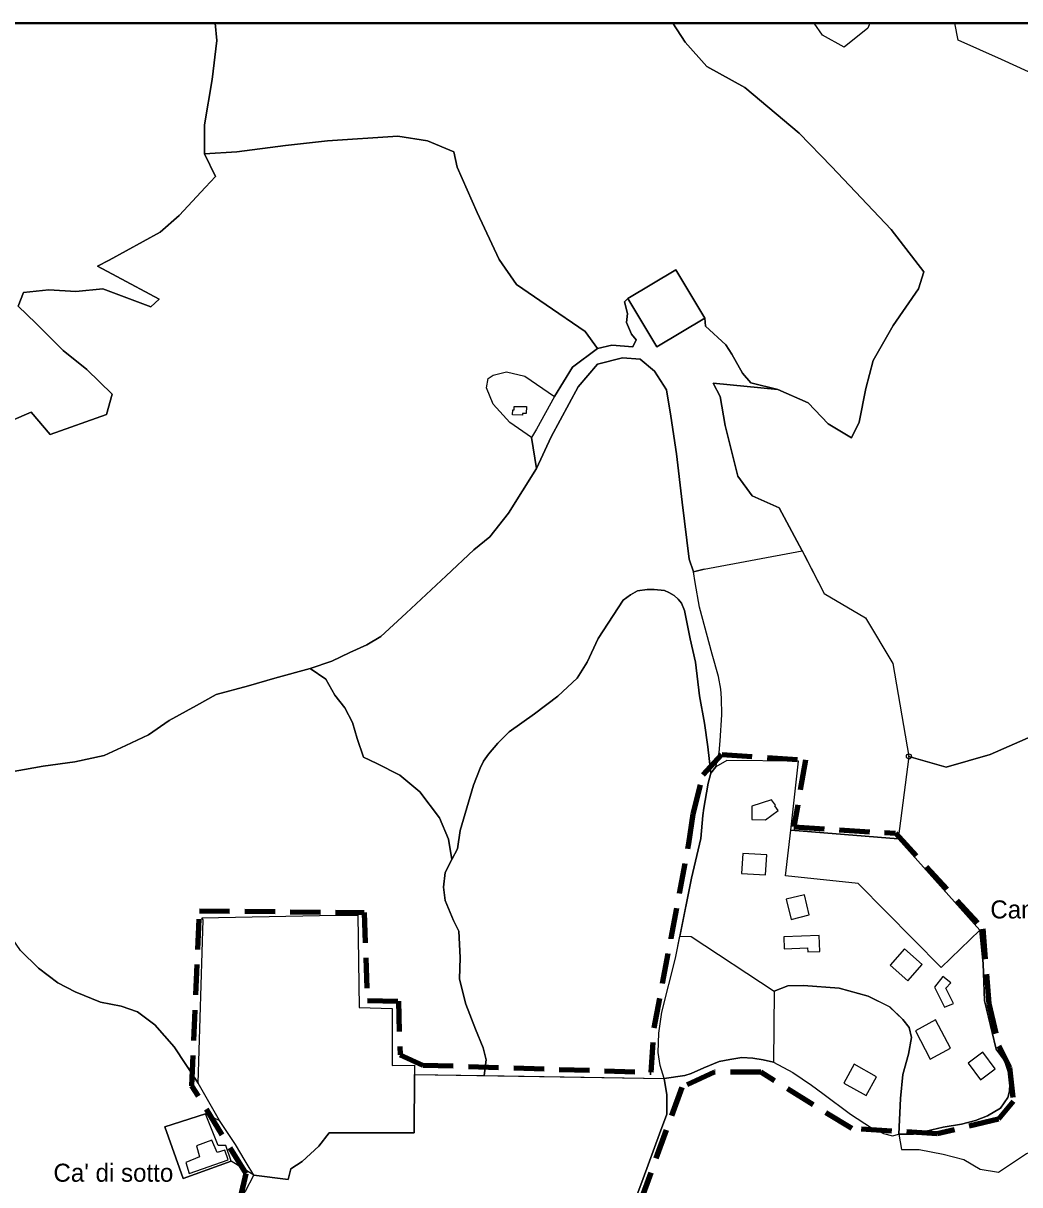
# Model space of a CAD drawing. Extents: x 650468 to 655025, y 889970 to 891591.
# Drawn here: x 654074 to 654626, y 890947 to 891591 of the extents above; entities that cross this region are included whole.
import ezdxf
from ezdxf.enums import TextEntityAlignment as Align

# ---------------------------------------------------------------- set-up
doc = ezdxf.new("R2010")
doc.units = 0
doc.header["$LTSCALE"] = 5.6
doc.header["$PDMODE"] = 32
doc.header["$PDSIZE"] = 2.8
doc.linetypes.add('MEDIUM_DASHED', pattern=[4.5, 3, -1.5])
for name, color, linetype, lineweight in [('11', 7, 'Continuous', 25), ('13', 7, 'Continuous', 25), ('19', 7, 'Continuous', 25), ('2', 7, 'Continuous', 25), ('20', 7, 'Continuous', 25), ('25', 7, 'Continuous', 25), ('31', 7, 'Continuous', 25), ('34', 7, 'Continuous', 25), ('35', 7, 'Continuous', 25), ('36', 7, 'Continuous', 25), ('37', 7, 'Continuous', 25), ('38', 7, 'Continuous', 25), ('6', 7, 'Continuous', 25), ('61', 7, 'Continuous', 35), ('7', 7, 'MEDIUM_DASHED', 100), ('9', 7, 'Continuous', 25)]:
    doc.layers.add(name, color=color, linetype=linetype, lineweight=lineweight)
doc.layers.add('60', color=7, linetype='Continuous')

msp = doc.modelspace()

# ---------------------------------------------------------------- linework, layer by layer
at = {"layer": '11'}
for points in [[(654526.26, 891055.98), (654506.53, 891057.59), (654497.91, 891057.32), (654490.26, 891054.44), (654489.91, 891015), (654500.51, 891009.32), (654510.97, 891002.25), (654517.19, 890997.65), (654532.5, 890986.24), (654544.32, 890978.54), (654550.97, 890975.53)], [(654550.97, 890975.53), (654555.85, 890974.15), (654559.47, 890975.16), (654560.32, 890994.86), (654561.56, 891008.17), (654564.69, 891019.43), (654566.47, 891028.65), (654565.2, 891034.24), (654561.54, 891038.72), (654554.31, 891045.73), (654542.37, 891051.66), (654526.26, 891055.98)]]:
    msp.add_lwpolyline(points, dxfattribs=at)
msp.add_lwpolyline([(654534.59, 891013.81), (654528.84, 891003.43), (654541.28, 890996.54), (654547.03, 891006.93)], close=True, dxfattribs=at)
at = {"layer": '13'}
msp.add_lwpolyline([(654536.84, 891114.1), (654496.59, 891118.38), (654499.46, 891143.65), (654558.94, 891138.76), (654604.36, 891088.18), (654582.8, 891067.48)], close=True, dxfattribs=at)
at = {"layer": '19'}
for points in [[(654429.2, 891006), (654427.06, 891013.1), (654425.98, 891020.44), (654426.23, 891030.98), (654427.86, 891042.64), (654435.45, 891072.74), (654437.93, 891084.93), (654444.24, 891084.76), (654490.26, 891054.43), (654489.92, 891015), (654484.13, 891016.32)], [(654459.83, 891015.42), (654451.3, 891011.91), (654444.28, 891008.65), (654440.77, 891007.64)], [(654472.29, 891017.59), (654465.59, 891016.55), (654459.83, 891015.42)], [(654484.13, 891016.32), (654478.38, 891017.18), (654472.29, 891017.59)], [(654197, 890943.46), (654201.61, 890952.4), (654220.7, 890949.89), (654222.24, 890955.88), (654228.41, 890959.87), (654237.67, 890968.35), (654243.33, 890975.84), (654290.52, 890975.84), (654290.66, 891008.15), (654429.2, 891006.01), (654430.69, 890996.86), (654430.8, 890986.12), (654426.65, 890975.27), (654417.62, 890950.54), (654399.53, 890902.06)], [(654429.2, 891006), (654440.77, 891007.64), (654429.2, 891006)]]:
    msp.add_lwpolyline(points, dxfattribs=at)
at = {"layer": '2'}
for points in [[(654355.64, 891361.3), (654343.64, 891369.61), (654334.42, 891379.77), (654330.73, 891389), (654331.65, 891394.08), (654334.42, 891395.93), (654341.8, 891397.77), (654351.95, 891395.47), (654368.48, 891384.09), (654358.44, 891365.96)], [(654346.09, 891378.51), (654352.88, 891378.5), (654352.75, 891374.65), (654350.73, 891374.6), (654350.73, 891373.83), (654345.19, 891373.88), (654345.24, 891376.67), (654346.1, 891376.7)], [(654174.81, 890986.42), (654152.28, 890979.05), (654162.37, 890950.57), (654189.01, 890960.03), (654186.08, 890968.75), (654181.78, 890968.75)], [(654163.9, 890959.42), (654165.81, 890953.25), (654187.43, 890960.84), (654185.5, 890966.13), (654181.37, 890964.98), (654178.39, 890971.71), (654169.84, 890968.53), (654171.57, 890962.48)]]:
    msp.add_lwpolyline(points, close=True, dxfattribs=at)
at = {"layer": '20'}
msp.add_lwpolyline([(654170.7, 891003.42), (654173.53, 891093.84), (654172.84, 891095.11), (654238.1, 891096.23), (654259.27, 891096.59), (654260.04, 891045.35), (654278.3, 891044.68), (654278.3, 891013.18), (654290.68, 891013.25), (654290.66, 891008.14), (654290.52, 890975.83), (654243.33, 890975.83), (654237.67, 890968.34), (654228.41, 890959.86), (654222.24, 890955.87), (654220.7, 890949.88), (654201.61, 890952.39), (654197.33, 890959.4), (654196.75, 890960.37), (654191.41, 890969.29), (654182.54, 890982.69)], close=True, dxfattribs=at)
at = {"layer": '25'}
msp.add_line((654304.53, 891150.42), (654309.67, 891138.66), dxfattribs=at)
for points in [[(654443.13, 891293.92), (654439.19, 891325.48), (654436.03, 891352.3), (654432.88, 891373.21), (654430.51, 891387.81), (654423.81, 891398.07), (654415.93, 891404.77), (654406.07, 891405.56), (654392.27, 891402.01), (654381.62, 891389.39)], [(654381.62, 891389.39), (654366.64, 891361.77), (654358.34, 891344.23), (654342.85, 891319.37), (654332.51, 891306.2), (654323.58, 891299), (654308.24, 891284.73), (654286.16, 891263.89), (654272.06, 891251.04)], [(654460.58, 891221.89), (654459.45, 891228.79), (654455.94, 891241.21), (654448.92, 891267.3), (654446.44, 891281.01), (654445.53, 891286.81), (654443.13, 891293.92)], [(654381.03, 891227.93), (654386.61, 891236.8), (654392.58, 891249.96), (654406.53, 891271.24), (654410.57, 891274.04), (654414.53, 891276.28), (654419.86, 891277.14), (654423.72, 891277.17), (654429.35, 891276.54), (654431.87, 891275.45), (654434.75, 891273.82), (654437.01, 891271.69), (654438.89, 891269.43), (654440.52, 891265.42), (654443.65, 891249.74), (654446.54, 891236.83), (654448.91, 891218.14), (654451.55, 891202.95), (654453.43, 891189.78), (654455.19, 891175.23), (654457.94, 891178.74)], [(654272.06, 891251.04), (654264.39, 891246.34), (654254.95, 891242.22)], [(654254.95, 891242.22), (654244.81, 891237.41), (654232.91, 891233.34)], [(654232.91, 891233.34), (654241.51, 891227.39), (654246.48, 891218.52), (654252.15, 891211.42), (654256.41, 891203.26), (654258.89, 891194.38), (654262.5, 891184.14), (654269.86, 891180.69), (654282.54, 891174.11), (654293.66, 891164.86), (654304.53, 891150.42)], [(654357.32, 891208.06), (654370.26, 891217.89), (654381.03, 891227.93)], [(654461.13, 891207.55), (654460.95, 891216.75), (654460.58, 891221.89)], [(654316.12, 891143.4), (654323.53, 891168.61), (654327.09, 891177.94), (654328.95, 891181.9), (654331.83, 891185.81), (654337.04, 891191.9), (654343.34, 891198.07), (654357.32, 891208.06)], [(654457.94, 891178.74), (654459.83, 891186.77), (654460.33, 891193.17), (654461.13, 891207.55)], [(654309.67, 891138.66), (654311.38, 891127.3), (654314.57, 891133.33), (654316.12, 891143.4)]]:
    msp.add_lwpolyline(points, dxfattribs=at)
at = {"layer": '31'}
for points in [[(654453.43, 891189.78), (654451.55, 891202.95), (654448.91, 891218.14), (654446.54, 891236.83), (654443.65, 891249.74), (654440.52, 891265.42), (654438.89, 891269.43), (654437.01, 891271.69), (654434.75, 891273.82), (654431.87, 891275.45), (654429.35, 891276.54), (654423.72, 891277.17), (654419.86, 891277.14), (654414.53, 891276.28), (654410.57, 891274.04), (654406.53, 891271.24), (654392.58, 891249.96), (654386.61, 891236.8), (654381.03, 891227.93)], [(654381.03, 891227.93), (654370.26, 891217.89), (654357.32, 891208.06)], [(654357.32, 891208.06), (654343.34, 891198.07), (654337.04, 891191.9), (654331.83, 891185.81), (654328.95, 891181.9), (654327.09, 891177.94), (654323.53, 891168.61), (654316.12, 891143.4)], [(654453.67, 891169.74), (654455.19, 891175.23), (654453.43, 891189.78)], [(654315.28, 891087.55), (654315.99, 891073), (654315.64, 891060.93), (654319.18, 891047.09), (654324.5, 891033.25), (654328.76, 891022.96), (654330.53, 891016.22), (654329.47, 891007.54), (654429.2, 891006), (654427.06, 891013.1), (654425.98, 891020.44), (654426.23, 891030.98), (654427.86, 891042.64), (654435.45, 891072.74), (654444.46, 891116.93), (654449.6, 891139.03), (654450.77, 891151.68), (654451.25, 891155.87), (654452.7, 891164.42), (654453.67, 891169.74)], [(654316.12, 891143.4), (654314.57, 891133.33), (654311.38, 891127.3), (654307.83, 891120.2), (654306.77, 891112.04), (654307.83, 891104.59), (654312.44, 891093.58), (654315.28, 891087.55)]]:
    msp.add_lwpolyline(points, dxfattribs=at)
at = {"layer": '34'}
for p, q in [((654451.42, 891288.44), (654445.53, 891286.81)), ((654463.91, 891182.3), (654457.94, 891178.74))]:
    msp.add_line(p, q, dxfattribs=at)
for points in [[(654451.42, 891288.44), (654505.84, 891298.44), (654517.93, 891274.94), (654540.98, 891261.33), (654556.01, 891236.06), (654565.03, 891184.54), (654558.94, 891138.75), (654499.46, 891143.64), (654503.73, 891181.86), (654463.91, 891182.3)], [(654460.58, 891221.89), (654459.45, 891228.79), (654455.94, 891241.21), (654448.92, 891267.3), (654446.44, 891281.01), (654445.53, 891286.81), (654451.42, 891288.44)], [(654461.13, 891207.55), (654460.95, 891216.75), (654460.58, 891221.89)], [(654457.94, 891178.74), (654459.83, 891186.77), (654460.33, 891193.17), (654461.13, 891207.55)]]:
    msp.add_lwpolyline(points, dxfattribs=at)
at = {"layer": '35'}
for points in [[(654723.35, 891275.91), (654713.14, 891269.98), (654703.64, 891271.74), (654691.89, 891279.49), (654681.27, 891273), (654666.24, 891247.72), (654655.21, 891218.56), (654655.63, 891201.68), (654634.17, 891196.2), (654610.12, 891185.51), (654585.63, 891178.66), (654565.03, 891184.54), (654558.94, 891138.75), (654604.36, 891088.17)], [(654232.91, 891233.34), (654213.2, 891227.88), (654198.73, 891223.66), (654180.66, 891218.84), (654169.81, 891212.81), (654154.75, 891204.37), (654143.3, 891196.53), (654130.65, 891190.5), (654118.59, 891185.08), (654102.33, 891181.46), (654084.85, 891179.05), (654060.75, 891174.83)], [(654262.5, 891184.14), (654258.89, 891194.38), (654256.41, 891203.26), (654252.15, 891211.42), (654246.48, 891218.52), (654241.51, 891227.39), (654232.91, 891233.34)], [(654315.28, 891087.55), (654312.44, 891093.58), (654307.83, 891104.59), (654306.77, 891112.04), (654307.83, 891120.2), (654311.38, 891127.3), (654309.67, 891138.66), (654304.53, 891150.42), (654293.66, 891164.86), (654282.54, 891174.11), (654269.86, 891180.69), (654262.5, 891184.14)], [(654170.7, 891003.42), (654173.53, 891093.84), (654172.84, 891095.11), (654238.1, 891096.23), (654259.27, 891096.59), (654260.04, 891045.35), (654278.3, 891044.68), (654278.3, 891013.18), (654290.68, 891013.25), (654290.66, 891008.14), (654329.47, 891007.54), (654330.53, 891016.22)], [(654324.5, 891033.25), (654319.18, 891047.09), (654315.64, 891060.93), (654315.99, 891073), (654315.28, 891087.55)], [(654604.36, 891088.17), (654606.19, 891069.58), (654606.98, 891049.07), (654613.39, 891022.17), (654618.04, 891015.89), (654620.59, 891008.2)], [(654072.27, 891076.98), (654082.2, 891067.04), (654092.89, 891059.02)], [(654092.89, 891059.02), (654102.44, 891054.05), (654116.57, 891048.32), (654128.02, 891046.03), (654137.18, 891042.97), (654146.73, 891035.72), (654157.42, 891023.49), (654170.7, 891003.42)], [(654330.53, 891016.22), (654328.76, 891022.96), (654324.5, 891033.25)], [(654440.77, 891007.64), (654444.28, 891008.65), (654451.3, 891011.91), (654459.83, 891015.42)], [(654459.83, 891015.42), (654465.59, 891016.55), (654472.29, 891017.59)], [(654472.29, 891017.59), (654478.38, 891017.18), (654484.13, 891016.32), (654489.92, 891015), (654489.91, 891014.99), (654500.51, 891009.31), (654510.97, 891002.24), (654517.19, 890997.64), (654532.5, 890986.23), (654544.32, 890978.53), (654550.97, 890975.52)], [(654620.59, 891008.2), (654620.91, 891002.74), (654620.79, 890998.86), (654619.82, 890995.48), (654615.7, 890989.49), (654608.63, 890985.18), (654601.98, 890982.67), (654594.08, 890980.67), (654583.93, 890979.04), (654574.53, 890976.78), (654567.51, 890975.15), (654559.47, 890975.15), (654560.8, 890966.6)], [(654398.63, 890870.86), (654393.91, 890872.3), (654388.18, 890871.68), (654391.04, 890877.21), (654399.53, 890902.05), (654417.62, 890950.53), (654426.65, 890975.26), (654430.8, 890986.11), (654430.69, 890996.85), (654429.2, 891006), (654440.77, 891007.64)], [(654614.69, 890954.07), (654630.14, 890964.31), (654692.09, 890985.03), (654685.79, 890974.85), (654668.7, 890958.56), (654656.4, 890945.47), (654631.8, 890929.74), (654613.87, 890916.44), (654587.96, 890904.47), (654561.39, 890894.84), (654542.79, 890888.85), (654523.19, 890882.21)], [(654550.97, 890975.52), (654555.85, 890974.14), (654559.47, 890975.15), (654560.8, 890966.6)], [(654560.8, 890966.6), (654570.67, 890966.6), (654583.91, 890964.06), (654595.44, 890960.94), (654604.46, 890955.58), (654614.69, 890954.07)], [(654560.8, 890966.6), (654570.67, 890966.6), (654583.91, 890964.06), (654595.44, 890960.94), (654604.46, 890955.58), (654614.69, 890954.07), (654630.14, 890964.31)]]:
    msp.add_lwpolyline(points, dxfattribs=at)
at = {"layer": '36'}
for points in [[(654056.47, 891366.24), (654078.16, 891375.45), (654088.61, 891362.95), (654119.83, 891374.16), (654123.07, 891385.36), (654108.99, 891399.14), (654095.84, 891409.66), (654080.73, 891424.8), (654070.84, 891434.15), (654073.82, 891441.86), (654087.95, 891443.22), (654102.92, 891442.36), (654117.85, 891443.86), (654144.46, 891433.9), (654149.18, 891438.13), (654125.56, 891450.58), (654114.9, 891456.38), (654121.47, 891459.67), (654149.68, 891475.18), (654160.2, 891484.4), (654174.8, 891500.1), (654180.29, 891506.06), (654174.34, 891518.7), (654174.34, 891534.8), (654178.49, 891559.96), (654181.08, 891581.59), (654180.27, 891591.08), (653618.27, 891591.08)], [(654631.32, 891564.12), (654616.29, 891570.92), (654592.24, 891581.61), (654590.46, 891591.08), (654543.37, 891591.08), (654542.13, 891588.42), (654529.11, 891577.73), (654517.08, 891584.53), (654512.48, 891591.08), (654434.08, 891591.08), (654440.93, 891580.64), (654452.95, 891567.03), (654473.99, 891555.37), (654504.06, 891530.09), (654522.09, 891511.62), (654555.16, 891476.63), (654573.2, 891453.3), (654570.22, 891443.86), (654556.2, 891423.44), (654545.17, 891404), (654541.16, 891388.45), (654537.37, 891369.8), (654533.15, 891361.23), (654520.12, 891369.01), (654509.1, 891380.67), (654492.37, 891388.06), (654456.37, 891391.56), (654460.37, 891384.06)], [(654460.37, 891384.06), (654463, 891368.03), (654470.02, 891339.84), (654478.12, 891329.02), (654493.07, 891322.34), (654507.09, 891296.1), (654517.93, 891274.94), (654540.98, 891261.33), (654556.01, 891236.06), (654565.03, 891184.54)], [(654565.03, 891184.54), (654585.63, 891178.66), (654610.12, 891185.51), (654634.17, 891196.2)]]:
    msp.add_lwpolyline(points, dxfattribs=at)
msp.add_point((654565.03, 891184.54), dxfattribs=at)
at = {"layer": '37'}
for points in [[(654477.25, 891391.72), (654492.37, 891388.06), (654509.1, 891380.67), (654520.12, 891369.01), (654533.15, 891361.23), (654537.37, 891369.8), (654541.16, 891388.45), (654545.17, 891404), (654556.2, 891423.44), (654570.22, 891443.86), (654573.2, 891453.3), (654555.16, 891476.63), (654522.09, 891511.62), (654504.06, 891530.09), (654473.99, 891555.37), (654452.95, 891567.03), (654440.93, 891580.64), (654434.08, 891591.08), (654180.27, 891591.08), (654181.08, 891581.59), (654178.49, 891559.96), (654174.34, 891534.8), (654174.34, 891518.7), (654192.27, 891519.85)], [(654368.48, 891384.08), (654378.42, 891400.3), (654392.27, 891410.69), (654385.34, 891420.22), (654363.7, 891434.95), (654347.25, 891446.21), (654337.72, 891460.07), (654325.6, 891486.06), (654314.35, 891511.19), (654312.61, 891519.85), (654297.9, 891525.91), (654281.45, 891528.51), (654242.48, 891525.91), (654219.11, 891523.32), (654192.27, 891519.85), (654174.34, 891518.7), (654180.29, 891506.06), (654174.8, 891500.1), (654160.2, 891484.4), (654149.68, 891475.18), (654121.47, 891459.67), (654114.9, 891456.38), (654125.56, 891450.58), (654149.18, 891438.13), (654144.46, 891433.9), (654117.85, 891443.86), (654102.92, 891442.36), (654087.95, 891443.22), (654073.82, 891441.86), (654070.84, 891434.15), (654080.73, 891424.8), (654095.84, 891409.66), (654108.99, 891399.14), (654123.07, 891385.36), (654119.83, 891374.16), (654088.61, 891362.95), (654078.16, 891375.45), (654056.47, 891366.24)], [(654192.27, 891519.85), (654219.11, 891523.32), (654242.48, 891525.91)], [(654242.48, 891525.91), (654281.45, 891528.51), (654297.9, 891525.91)], [(654297.9, 891525.91), (654312.61, 891519.85), (654314.35, 891511.19), (654325.6, 891486.06)], [(654325.6, 891486.06), (654337.72, 891460.07), (654347.25, 891446.21), (654363.7, 891434.95), (654385.34, 891420.22), (654392.27, 891410.69)], [(654392.27, 891410.69), (654400.12, 891412.55), (654411.79, 891411.6), (654413.68, 891415.55), (654411.16, 891418.7), (654408.32, 891425.17), (654408.95, 891430.07), (654407.22, 891436.54), (654409.1, 891438.47), (654435.62, 891454.38), (654451.73, 891427.53), (654452.18, 891423.12), (654463.37, 891412.71)], [(654409.1, 891438.47), (654407.22, 891436.54), (654408.95, 891430.07), (654408.32, 891425.17), (654411.16, 891418.7), (654413.68, 891415.55), (654411.79, 891411.6), (654400.12, 891412.55), (654392.27, 891410.69)], [(654409.1, 891438.47), (654407.22, 891436.54), (654408.95, 891430.07), (654408.32, 891425.17), (654411.16, 891418.7), (654413.68, 891415.55), (654411.79, 891411.6), (654400.12, 891412.55), (654392.27, 891410.69)], [(654492.37, 891388.06), (654477.25, 891391.72), (654472.68, 891397.09), (654466.69, 891407.66), (654463.37, 891412.71), (654452.18, 891423.12), (654451.73, 891427.53), (654425.21, 891411.62), (654409.1, 891438.47)], [(654451.73, 891427.53), (654452.18, 891423.12), (654463.37, 891412.71), (654466.69, 891407.66), (654472.68, 891397.09), (654477.25, 891391.72), (654492.37, 891388.06)], [(654392.27, 891410.69), (654378.42, 891400.3), (654368.48, 891384.08), (654358.44, 891365.95), (654355.64, 891361.29), (654358.34, 891344.23)], [(654463.37, 891412.71), (654466.69, 891407.66), (654472.68, 891397.09), (654477.25, 891391.72)], [(654381.62, 891389.39), (654392.27, 891402.01), (654406.07, 891405.56), (654415.93, 891404.77), (654423.81, 891398.07), (654430.51, 891387.81), (654432.88, 891373.21)], [(654254.95, 891242.22), (654264.39, 891246.34), (654272.06, 891251.04), (654286.16, 891263.89), (654308.24, 891284.73), (654323.58, 891299), (654332.51, 891306.2), (654342.85, 891319.37), (654358.34, 891344.23), (654355.64, 891361.29), (654343.64, 891369.6), (654334.42, 891379.76), (654330.73, 891388.99), (654331.65, 891394.07), (654334.42, 891395.92), (654341.8, 891397.76), (654351.95, 891395.46), (654368.48, 891384.08)], [(654358.34, 891344.23), (654366.64, 891361.77), (654381.62, 891389.39)], [(654432.88, 891373.21), (654436.03, 891352.3), (654439.19, 891325.48), (654443.13, 891293.92), (654445.53, 891286.81), (654451.42, 891288.44), (654505.84, 891298.44), (654493.07, 891322.34), (654478.12, 891329.02), (654470.02, 891339.84), (654463, 891368.03), (654460.37, 891384.06), (654456.37, 891391.56), (654492.37, 891388.06)], [(654232.91, 891233.34), (654244.81, 891237.41), (654254.95, 891242.22)], [(654198.73, 891223.66), (654213.2, 891227.88), (654232.91, 891233.34)], [(654004.69, 891141.92), (654003.16, 891147.66), (654003.51, 891151.92), (654011.94, 891156.74), (654024.6, 891163.37), (654039.66, 891169.4), (654060.75, 891174.83), (654084.85, 891179.05), (654102.33, 891181.46), (654118.59, 891185.08), (654130.65, 891190.5), (654143.3, 891196.53), (654154.75, 891204.37), (654169.81, 891212.81), (654180.66, 891218.84), (654198.73, 891223.66)], [(654092.89, 891059.02), (654082.2, 891067.04), (654072.27, 891076.98), (654064.64, 891088.06), (654054.33, 891110.98), (654046.31, 891121.29), (654037.53, 891125.11), (654023.02, 891133.14), (654010.04, 891138.49), (654004.69, 891141.92)], [(654170.7, 891003.42), (654157.42, 891023.49), (654146.73, 891035.72), (654137.18, 891042.97), (654128.02, 891046.03), (654116.57, 891048.32), (654102.44, 891054.05), (654092.89, 891059.02)], [(654154.4, 890736.15), (654160.16, 890761.07), (654184.05, 890864.37), (654187.87, 890880.92), (654192.08, 890888.73), (654191.09, 890895.11), (654190.43, 890902.12), (654192.08, 890919.35), (654194.7, 890940.27), (654197, 890943.45), (654201.61, 890952.39), (654189.01, 890960.03), (654162.37, 890950.57), (654152.28, 890979.05), (654174.81, 890986.42), (654182.54, 890982.69), (654170.7, 891003.42)]]:
    msp.add_lwpolyline(points, dxfattribs=at)
at = {"layer": '38'}
msp.add_lwpolyline([(654435.62, 891454.38), (654409.1, 891438.47), (654425.21, 891411.62), (654451.73, 891427.53)], close=True, dxfattribs=at)
at = {"layer": '6'}
msp.add_lwpolyline([(654488.82, 891160.49), (654477.86, 891157), (654477.78, 891149.5), (654485.42, 891149.42), (654492.43, 891154.53), (654490.55, 891157.1), (654491.03, 891157.46)], close=True, dxfattribs=at)
at = {"layer": '61', "lineweight": 40}
msp.add_lwpolyline([(653618.27, 891591.08), (655025.2, 891591.08), (655025.2, 889969.62), (653618.27, 889969.62)], close=True, dxfattribs=at)
at = {"layer": '7'}
for points in [[(654445.39, 891152.42), (654450.87, 891174.27), (654461.13, 891185.52), (654507.55, 891182.58), (654501.2, 891145.42), (654557.6, 891141.88), (654606.07, 891088.92), (654609.3, 891047.26), (654614.85, 891024.12), (654620.87, 891012.09), (654622.82, 890993.13), (654614.72, 890983.4), (654580.68, 890975.29), (654533.26, 890978.14), (654482.8, 891009.39), (654457.18, 891009.39), (654439, 891001), (654395.52, 890881.18)], [(654182.51, 890891.6), (654197.39, 890953.2), (654167.25, 891001.92), (654171.42, 891098.9), (654262.78, 891097.98), (654264.63, 891049.25), (654281.79, 891048.79), (654282.72, 891019.09), (654295.43, 891013.4), (654421.96, 891009.4), (654423.69, 891033.94), (654433.11, 891083.83), (654442.96, 891136.21), (654445.39, 891152.42)]]:
    msp.add_lwpolyline(points, dxfattribs=at)
at = {"layer": '9'}
for points in [[(654463.91, 891182.3), (654457.94, 891178.74), (654455.19, 891175.23), (654453.67, 891169.74), (654452.7, 891164.42), (654451.25, 891155.87), (654450.77, 891151.68), (654449.6, 891139.03), (654444.46, 891116.93), (654437.93, 891084.93), (654444.24, 891084.76), (654490.26, 891054.43), (654497.92, 891057.32), (654506.53, 891057.58), (654526.26, 891055.97), (654542.38, 891051.66), (654554.32, 891045.73), (654561.55, 891038.72), (654565.2, 891034.23), (654566.47, 891028.64), (654564.69, 891019.42), (654561.56, 891008.16), (654560.32, 890994.85), (654559.48, 890975.16), (654567.51, 890975.15), (654574.53, 890976.78), (654583.93, 890979.04), (654594.08, 890980.67), (654601.98, 890982.67)], [(654499.46, 891143.64), (654503.73, 891181.86), (654463.91, 891182.3)], [(654619.82, 890995.48), (654620.79, 890998.86), (654620.91, 891002.74), (654620.59, 891008.2), (654618.02, 891015.94), (654613.39, 891022.17), (654606.96, 891049.12), (654606.19, 891069.58), (654604.36, 891088.17), (654582.8, 891067.47), (654536.84, 891114.09), (654496.59, 891118.37), (654499.46, 891143.64)], [(654601.98, 890982.67), (654608.63, 890985.18), (654615.7, 890989.49), (654619.82, 890995.48)]]:
    msp.add_lwpolyline(points, dxfattribs=at)
for points in [[(654472.88, 891130.67), (654472.1, 891119.66), (654485.43, 891118.91), (654486.21, 891129.92)], [(654496.96, 891105.31), (654499.7, 891094.14), (654509.72, 891096.6), (654506.98, 891107.77)], [(654495.56, 891084.41), (654495.84, 891077.76), (654508.77, 891078.3), (654508.86, 891076.14), (654515.58, 891076.42), (654515.21, 891085.22)], [(654562.6, 891077.86), (654554.64, 891068.81), (654564.47, 891060.16), (654572.43, 891069.21)], [(654583.82, 891062.47), (654579.15, 891056.62), (654584.64, 891045.44), (654589.7, 891047.54), (654585.46, 891056.09), (654588.21, 891059.01)], [(654579.82, 891038.47), (654568.57, 891032.36), (654576.84, 891016.59), (654588.09, 891022.7)], [(654606.05, 891020.53), (654597.82, 891014.41), (654604.68, 891005.19), (654612.91, 891011.32)]]:
    msp.add_lwpolyline(points, close=True, dxfattribs=at)

# ---------------------------------------------------------------- texts
at = {"layer": '60'}
for s, p in [('Campo  Ferraio', (654656.6, 891094.69)), ("Ca' di sotto", (654123.72, 890948.69))]:
    msp.add_text(s, height=10, dxfattribs=at).set_placement(p, align=Align.CENTER)

doc.saveas('drawing.dxf')
